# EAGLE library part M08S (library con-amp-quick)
AMP QUICK CONNECTOR
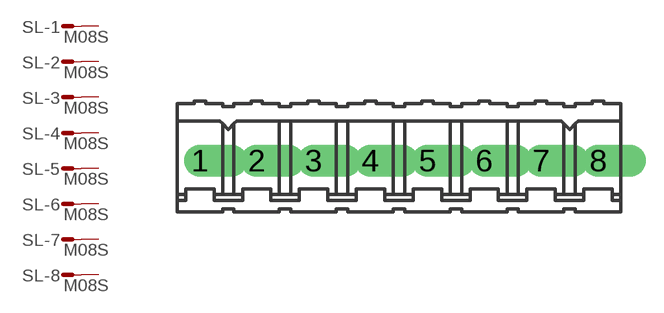
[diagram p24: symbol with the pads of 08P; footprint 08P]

Designator prefix SL; gates -1=M -2=M -3=M -4=M -5=M -6=M -7=M -8=M

## M08S  [08P]
1  -1:S  pas
2  -2:S  pas
3  -3:S  pas
4  -4:S  pas
5  -5:S  pas
6  -6:S  pas
7  -7:S  pas
8  -8:S  pas

## Footprint 08P (pad centres in mm)
AMP QUICK CONNECTOR
drill 0.914 offset: 1 -8.89,0; 2 -6.35,0; 3 -3.81,0; 4 -1.27,0; 5 1.27,0; 6 3.81,0; 7 6.35,0; 8 8.89,0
